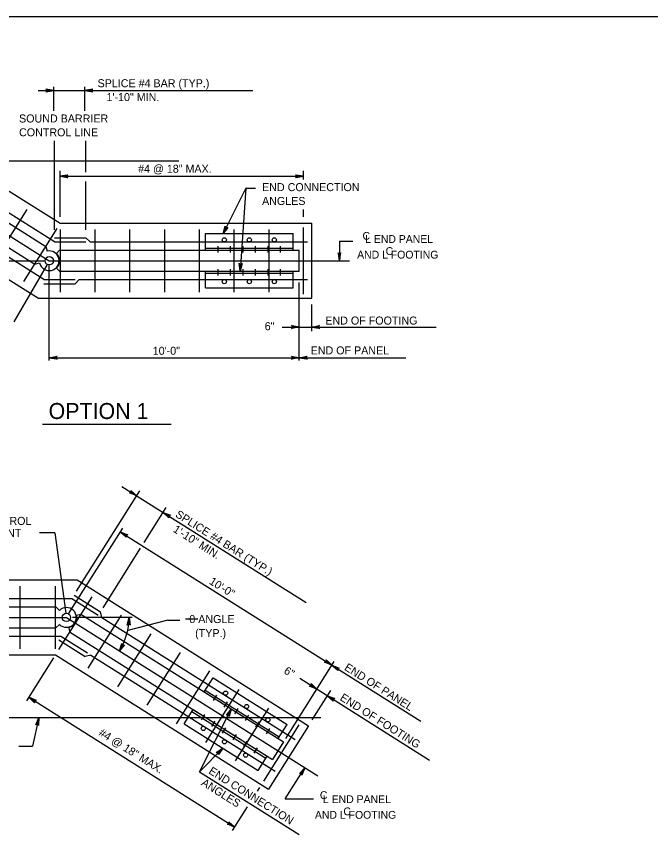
# Model space of a CAD drawing. Extents: x 3385 to 6532, y -616 to 1166.
# Drawn here: x 5641 to 5884.5, y -351.4 to -37.3 of the extents above; entities that cross this region are included whole.
import ezdxf

# ---------------------------------------------------------------- set-up
doc = ezdxf.new("R2010")
doc.units = 0
doc.layers.add('1', color=7, linetype='Continuous')
doc.layers.add('2', color=7, linetype='Continuous')

msp = doc.modelspace()

# ---------------------------------------------------------------- linework, layer by layer
at = {"layer": '1'}
for p, q in [((5649.41, -65.78), (5731.79, -65.78)), ((5655.36, -73.58), (5655.36, -64.39)), ((5667.36, -73.58), (5667.36, -64.39)), ((5565.2, -75.36), (5653.63, -131.12)), ((5655.72, -119.26), (5655.72, -85.08)), ((5667.72, -97.07), (5667.72, -85.08)), ((5616.77, -90.85), (5657.79, -116.72)), ((5554.94, -92.72), (5703.36, -92.72)), ((5655.71, -123.92), (5612.93, -96.94)), ((5657.79, -114.23), (5657.79, -96.66)), ((5751.24, -99.9), (5751.24, -96.66)), ((5611.22, -99.65), (5652.38, -125.6)), ((5657.79, -98.7), (5751.24, -98.7)), ((5667.72, -119.26), (5667.72, -100.7)), ((5729.06, -103.25), (5720.37, -120.72)), ((5729.06, -103.25), (5726.94, -135.12)), ((5729.06, -103.25), (5732.82, -103.25)), ((5606.95, -106.42), (5648.11, -132.37)), ((5651.55, -138.32), (5605.25, -109.12)), ((5645.01, -111.5), (5632.21, -131.8)), ((5751.24, -114.23), (5751.24, -111.41)), ((5601.41, -115.21), (5649.47, -145.52)), ((5656.51, -118.75), (5643.71, -139.05)), ((5657.79, -116.72), (5754.44, -116.72)), ((5657.79, -119.12), (5657.79, -143.12)), ((5671.14, -119.12), (5671.14, -143.12)), ((5684.49, -119.12), (5684.49, -143.12)), ((5697.84, -119.12), (5697.84, -143.12)), ((5711.19, -119.12), (5711.19, -143.12)), ((5724.54, -119.12), (5724.54, -143.12)), ((5737.89, -119.12), (5737.89, -143.12)), ((5751.24, -143.92), (5751.24, -118.32)), ((5754.44, -145.52), (5754.44, -116.72)), ((5655.71, -122.32), (5667.72, -122.32)), ((5669.32, -123.92), (5667.72, -122.32)), ((5713.63, -127.12), (5713.63, -120.72)), ((5713.63, -120.72), (5747.24, -120.72)), ((5747.24, -127.12), (5747.24, -120.72)), ((5652.38, -125.6), (5652.79, -127.41)), ((5655.71, -123.92), (5667.72, -123.92)), ((5669.32, -123.92), (5752.84, -123.92)), ((5718.44, -127.92), (5718.44, -125.52)), ((5723.24, -127.92), (5723.24, -125.52)), ((5728.04, -127.92), (5728.04, -125.52)), ((5732.84, -127.92), (5732.84, -125.52)), ((5737.64, -127.92), (5737.64, -125.52)), ((5742.44, -127.92), (5742.44, -125.52)), ((5765.08, -123.57), (5770.17, -123.57)), ((5765.08, -123.57), (5765.08, -131.12)), ((5656.46, -128.29), (5657.63, -127.12)), ((5657.63, -127.12), (5749.64, -127.12)), ((5713.63, -126.32), (5747.24, -126.32)), ((5713.63, -127.12), (5747.24, -127.12)), ((5749.64, -135.12), (5749.64, -127.12)), ((5628.32, -131.12), (5652.03, -131.12)), ((5653.63, -131.12), (5653.63, -131.12)), ((5653.63, -131.12), (5768.94, -131.12)), ((5652.83, -132.5), (5640.07, -154.59)), ((5648.12, -132.37), (5649.93, -131.96)), ((5653.63, -169.46), (5653.63, -132.72)), ((5656.46, -133.95), (5657.63, -135.12)), ((5718.44, -136.72), (5718.44, -134.32)), ((5723.24, -136.72), (5723.24, -134.32)), ((5728.04, -136.72), (5728.04, -134.32)), ((5732.84, -136.72), (5732.84, -134.32)), ((5737.64, -136.72), (5737.64, -134.32)), ((5742.44, -136.72), (5742.44, -134.32)), ((5657.63, -135.12), (5749.64, -135.12)), ((5713.63, -141.52), (5713.63, -135.12)), ((5713.63, -135.12), (5747.24, -135.12)), ((5713.63, -135.92), (5747.24, -135.92)), ((5747.24, -141.52), (5747.24, -135.12)), ((5651.55, -138.32), (5663.56, -138.32)), ((5651.55, -139.92), (5663.56, -139.92)), ((5665.16, -138.32), (5663.56, -139.92)), ((5665.16, -138.32), (5752.84, -138.32)), ((5749.64, -169.46), (5749.64, -139.49)), ((5713.63, -141.52), (5747.24, -141.52)), ((5649.47, -145.52), (5754.44, -145.52)), ((5754.44, -158.18), (5754.44, -147.93)), ((5743, -156.56), (5802.15, -156.56)), ((5653.63, -168.37), (5790.52, -168.37)), ((5651.07, -193.79), (5700.5, -193.79)), ((5664.15, -257.91), (5688.38, -219.49)), ((5681.55, -217.73), (5752.25, -262.31)), ((5690.07, -239.31), (5698.53, -225.89)), ((5655.76, -235.56), (5649.85, -235.56)), ((5655.76, -235.56), (5660.01, -266.44)), ((5661.09, -266.67), (5681.85, -233.74)), ((5680.93, -235.19), (5796.26, -307.9)), ((5674.31, -264.31), (5688.69, -241.49)), ((5602.42, -253.63), (5664.39, -253.63)), ((5664.39, -253.63), (5753.18, -309.61)), ((5642.5, -280.03), (5642.5, -256.03)), ((5656.07, -280.03), (5656.07, -256.03)), ((5657.35, -280.4), (5670.15, -260.09)), ((5663.17, -259.47), (5673.32, -265.87)), ((5602.42, -260.83), (5662.31, -260.83)), ((5662.31, -260.83), (5672.47, -267.23)), ((5602.42, -264.03), (5656.23, -264.03)), ((5656.23, -264.03), (5657.55, -265.34)), ((5664.13, -267.14), (5665.75, -266.78)), ((5665.75, -266.78), (5743.58, -315.84)), ((5673.82, -268.08), (5673.32, -265.87)), ((5564.37, -268.03), (5660.23, -268.03)), ((5660.23, -268.03), (5756.75, -328.88)), ((5660.23, -268.03), (5660.23, -268.03)), ((5685.5, -268.03), (5662.63, -268.03)), ((5668.64, -287.52), (5681.44, -267.21)), ((5673.82, -268.08), (5747.99, -314.84)), ((5699.22, -269.15), (5683.75, -273.09)), ((5699.22, -269.15), (5703.77, -269.15)), ((5710.7, -268.7), (5705.92, -268.7)), ((5602.42, -272.03), (5656.23, -272.03)), ((5656.23, -272.03), (5657.55, -270.71)), ((5661.12, -271.93), (5661.48, -273.54)), ((5602.42, -275.23), (5658.15, -275.23)), ((5658.15, -275.23), (5668.31, -281.63)), ((5661.48, -273.55), (5739.31, -322.61)), ((5679.94, -294.64), (5692.74, -274.33)), ((5657.3, -276.58), (5667.45, -282.98)), ((5602.42, -282.43), (5656.07, -282.43)), ((5656.07, -282.43), (5737.82, -333.97)), ((5669.66, -282.48), (5667.45, -282.98)), ((5669.66, -282.48), (5740.31, -327.02)), ((5691.23, -301.75), (5704.03, -281.45)), ((5645, -299.99), (5655.39, -283.51)), ((5744.44, -314.47), (5763.06, -284.94)), ((5702.52, -308.87), (5715.32, -288.57)), ((5713.12, -296.64), (5716.54, -291.23)), ((5716.54, -291.23), (5744.96, -309.15)), ((5749.79, -291.36), (5799.64, -322.79)), ((5713.12, -296.64), (5741.55, -314.56)), ((5713.55, -295.96), (5741.97, -313.88)), ((5713.81, -315.99), (5726.61, -295.69)), ((5716.75, -299.88), (5718.03, -297.85)), ((5754.64, -307.3), (5761.7, -296.09)), ((5645.82, -298.69), (5724.86, -348.53)), ((5720.81, -302.44), (5722.09, -300.41)), ((5705.44, -308.83), (5708.85, -303.41)), ((5708.43, -304.09), (5736.85, -322.01)), ((5708.85, -303.41), (5737.28, -321.33)), ((5711.36, -327.3), (5723.52, -303.19)), ((5724.87, -305), (5726.15, -302.97)), ((5725.1, -323.11), (5737.9, -302.81)), ((5602.42, -306.43), (5757.95, -306.43)), ((5649.69, -306.43), (5647.16, -317.45)), ((5712.06, -307.33), (5713.34, -305.3)), ((5728.93, -307.56), (5730.21, -305.53)), ((5705.44, -308.83), (5733.86, -326.75)), ((5716.12, -309.89), (5717.4, -307.86)), ((5720.18, -312.45), (5721.46, -310.42)), ((5733, -310.12), (5734.27, -308.09)), ((5735.97, -330.91), (5749.62, -309.25)), ((5737.06, -312.68), (5738.34, -310.65)), ((5753.18, -309.61), (5737.82, -333.97)), ((5741.55, -314.56), (5744.96, -309.15)), ((5724.24, -315.01), (5725.52, -312.98)), ((5728.3, -317.57), (5729.58, -315.54)), ((5743.58, -315.84), (5739.31, -322.61)), ((5641.97, -317.45), (5647.16, -317.45)), ((5711.36, -327.3), (5720.26, -318.17)), ((5732.36, -320.13), (5733.64, -318.1)), ((5733.86, -326.75), (5737.28, -321.33)), ((5744.21, -337.69), (5751.75, -325.73)), ((5711.36, -327.3), (5749.61, -351.41)), ((5733.59, -334.67), (5734.45, -333.31)), ((5744.21, -337.69), (5755.07, -337.69)), ((5724.04, -349.83), (5729.8, -340.69))]:
    msp.add_line(p, q, dxfattribs=at)
for points in [[(5655.36, -65.78), (5652.38, -65.22), (5652.61, -65.38), (5652.73, -65.58), (5652.76, -65.78), (5652.73, -65.98), (5652.61, -66.18), (5652.38, -66.34), (5655.36, -65.78), (5652.61, -66.18), (5652.73, -65.98), (5655.36, -65.78), (5652.76, -65.78), (5652.73, -65.58), (5655.36, -65.78), (5652.61, -65.38)], [(5667.36, -65.78), (5670.34, -66.34), (5670.11, -66.18), (5670, -65.98), (5669.96, -65.78), (5670, -65.58), (5670.11, -65.38), (5670.34, -65.22), (5667.36, -65.78), (5670.11, -65.38), (5670, -65.58), (5667.36, -65.78), (5669.96, -65.78), (5670, -65.98), (5667.36, -65.78), (5670.11, -66.18)], [(5657.79, -98.7), (5660.78, -98.14), (5660.66, -98.22), (5660.55, -98.3), (5660.49, -98.4), (5660.43, -98.5), (5660.41, -98.6), (5660.39, -98.7), (5660.41, -98.8), (5660.43, -98.9), (5660.49, -99), (5660.55, -99.1), (5660.66, -99.18), (5660.78, -99.26), (5657.79, -98.7), (5660.66, -99.18), (5660.55, -99.1), (5657.79, -98.7), (5660.49, -99), (5660.43, -98.9), (5657.79, -98.7), (5660.41, -98.8), (5660.39, -98.7), (5657.79, -98.7), (5660.41, -98.6), (5660.43, -98.5), (5657.79, -98.7), (5660.49, -98.4), (5660.55, -98.3), (5657.79, -98.7), (5660.66, -98.22)], [(5751.24, -98.7), (5748.26, -99.26), (5748.37, -99.18), (5748.49, -99.1), (5748.55, -99), (5748.6, -98.9), (5748.62, -98.8), (5748.64, -98.7), (5748.62, -98.6), (5748.6, -98.5), (5748.55, -98.4), (5748.49, -98.3), (5748.37, -98.22), (5748.26, -98.14), (5751.24, -98.7), (5748.37, -98.22), (5748.49, -98.3), (5751.24, -98.7), (5748.55, -98.4), (5748.6, -98.5), (5751.24, -98.7), (5748.62, -98.6), (5748.64, -98.7), (5751.24, -98.7), (5748.62, -98.8), (5748.6, -98.9), (5751.24, -98.7), (5748.55, -99), (5748.49, -99.1), (5751.24, -98.7), (5748.37, -99.18)], [(5720.37, -120.72), (5721.2, -117.8), (5721.22, -117.94), (5721.24, -118.07), (5721.3, -118.17), (5721.37, -118.27), (5721.45, -118.33), (5721.53, -118.39), (5721.63, -118.42), (5721.73, -118.45), (5721.84, -118.44), (5721.96, -118.43), (5722.08, -118.36), (5722.2, -118.3), (5720.37, -120.72), (5722.08, -118.36), (5721.96, -118.43), (5720.37, -120.72), (5721.84, -118.44), (5721.73, -118.45), (5720.37, -120.72), (5721.63, -118.42), (5721.53, -118.39), (5720.37, -120.72), (5721.45, -118.33), (5721.37, -118.27), (5720.37, -120.72), (5721.3, -118.17), (5721.24, -118.07), (5720.37, -120.72), (5721.22, -117.94)], [(5765.08, -131.12), (5765.64, -128.14), (5765.48, -128.37), (5765.28, -128.48), (5765.08, -128.52), (5764.88, -128.48), (5764.68, -128.37), (5764.53, -128.14), (5765.08, -131.12), (5764.68, -128.37), (5764.88, -128.48), (5765.08, -131.12), (5765.08, -128.52), (5765.28, -128.48), (5765.08, -131.12), (5765.48, -128.37)], [(5726.94, -135.12), (5726.58, -132.11), (5726.72, -132.35), (5726.91, -132.48), (5727.11, -132.52), (5727.31, -132.5), (5727.52, -132.4), (5727.69, -132.18), (5726.94, -135.12), (5727.52, -132.4), (5727.31, -132.5), (5726.94, -135.12), (5727.11, -132.52), (5726.91, -132.48), (5726.94, -135.12), (5726.72, -132.35)], [(5749.64, -156.56), (5746.65, -157.12), (5746.88, -156.96), (5747, -156.76), (5747.04, -156.56), (5747, -156.36), (5746.88, -156.16), (5746.65, -156), (5749.64, -156.56), (5746.88, -156.16), (5747, -156.36), (5749.64, -156.56), (5747.04, -156.56), (5747, -156.76), (5749.64, -156.56), (5746.88, -156.96)], [(5754.44, -156.56), (5757.42, -156), (5757.19, -156.16), (5757.07, -156.36), (5757.04, -156.56), (5757.07, -156.76), (5757.19, -156.96), (5757.42, -157.12), (5754.44, -156.56), (5757.19, -156.96), (5757.07, -156.76), (5754.44, -156.56), (5757.04, -156.56), (5757.07, -156.36), (5754.44, -156.56), (5757.19, -156.16)], [(5653.63, -168.37), (5656.62, -167.81), (5656.39, -167.97), (5656.27, -168.17), (5656.23, -168.37), (5656.27, -168.57), (5656.39, -168.77), (5656.62, -168.93), (5653.63, -168.37), (5656.39, -168.77), (5656.27, -168.57), (5653.63, -168.37), (5656.23, -168.37), (5656.27, -168.17), (5653.63, -168.37), (5656.39, -167.97)], [(5749.64, -168.37), (5746.65, -168.93), (5746.88, -168.77), (5747, -168.57), (5747.04, -168.37), (5747, -168.17), (5746.88, -167.97), (5746.65, -167.81), (5749.64, -168.37), (5746.88, -167.97), (5747, -168.17), (5749.64, -168.37), (5747.04, -168.37), (5747, -168.57), (5749.64, -168.37), (5746.88, -168.77)], [(5749.64, -168.37), (5752.62, -167.81), (5752.39, -167.97), (5752.27, -168.17), (5752.24, -168.37), (5752.27, -168.57), (5752.39, -168.77), (5752.62, -168.93), (5749.64, -168.37), (5752.39, -168.77), (5752.27, -168.57), (5749.64, -168.37), (5752.24, -168.37), (5752.27, -168.17), (5749.64, -168.37), (5752.39, -167.97)], [(5687.23, -221.31), (5684.41, -220.19), (5684.69, -220.18), (5684.89, -220.07), (5685.03, -219.92), (5685.11, -219.74), (5685.11, -219.5), (5685, -219.25), (5687.23, -221.31), (5685.11, -219.5), (5685.11, -219.74), (5687.23, -221.31), (5685.03, -219.92), (5684.89, -220.07), (5687.23, -221.31), (5684.69, -220.18)], [(5697.38, -227.71), (5700.2, -228.83), (5699.92, -228.84), (5699.72, -228.95), (5699.58, -229.1), (5699.5, -229.29), (5699.5, -229.52), (5699.61, -229.78), (5697.38, -227.71), (5699.5, -229.52), (5699.5, -229.29), (5697.38, -227.71), (5699.58, -229.1), (5699.72, -228.95), (5697.38, -227.71), (5699.92, -228.84)], [(5680.93, -235.19), (5683.76, -236.31), (5683.48, -236.32), (5683.27, -236.43), (5683.13, -236.58), (5683.06, -236.77), (5683.05, -237), (5683.16, -237.26), (5680.93, -235.19), (5683.05, -237), (5683.06, -236.77), (5680.93, -235.19), (5683.13, -236.58), (5683.27, -236.43), (5680.93, -235.19), (5683.48, -236.32)], [(5684.29, -268.03), (5684.68, -271.04), (5684.53, -270.8), (5684.34, -270.67), (5684.14, -270.62), (5683.94, -270.65), (5683.74, -270.75), (5683.56, -270.97), (5684.29, -268.03), (5683.74, -270.75), (5683.94, -270.65), (5684.29, -268.03), (5684.14, -270.62), (5684.34, -270.67), (5684.29, -268.03), (5684.53, -270.8)], [(5680.59, -280.86), (5681.54, -277.98), (5681.57, -278.26), (5681.69, -278.46), (5681.84, -278.58), (5682.04, -278.65), (5682.27, -278.64), (5682.52, -278.52), (5680.59, -280.86), (5682.27, -278.64), (5682.04, -278.65), (5680.59, -280.86), (5681.84, -278.58), (5681.69, -278.46), (5680.59, -280.86), (5681.57, -278.26)], [(5762.14, -286.39), (5759.32, -285.27), (5759.6, -285.26), (5759.81, -285.16), (5759.94, -285.01), (5760.02, -284.82), (5760.03, -284.59), (5759.92, -284.33), (5762.14, -286.39), (5760.03, -284.59), (5760.02, -284.82), (5762.14, -286.39), (5759.94, -285.01), (5759.81, -285.16), (5762.14, -286.39), (5759.6, -285.26)], [(5762.14, -286.39), (5764.96, -287.51), (5764.68, -287.52), (5764.48, -287.63), (5764.34, -287.78), (5764.26, -287.97), (5764.26, -288.2), (5764.37, -288.46), (5762.14, -286.39), (5764.26, -288.2), (5764.26, -287.97), (5762.14, -286.39), (5764.34, -287.78), (5764.48, -287.63), (5762.14, -286.39), (5764.68, -287.52)], [(5756.39, -295.52), (5753.57, -294.4), (5753.85, -294.39), (5754.05, -294.29), (5754.19, -294.13), (5754.27, -293.95), (5754.27, -293.71), (5754.16, -293.46), (5756.39, -295.52), (5754.27, -293.71), (5754.27, -293.95), (5756.39, -295.52), (5754.19, -294.13), (5754.05, -294.29), (5756.39, -295.52), (5753.85, -294.39)], [(5760.45, -298.08), (5763.27, -299.2), (5762.99, -299.21), (5762.78, -299.32), (5762.65, -299.47), (5762.57, -299.66), (5762.56, -299.89), (5762.67, -300.14), (5760.45, -298.08), (5762.56, -299.89), (5762.57, -299.66), (5760.45, -298.08), (5762.65, -299.47), (5762.78, -299.32), (5760.45, -298.08), (5762.99, -299.21)], [(5645.82, -298.69), (5648.64, -299.81), (5648.5, -299.82), (5648.36, -299.82), (5648.26, -299.87), (5648.15, -299.93), (5648.08, -300), (5648.02, -300.08), (5647.98, -300.17), (5647.94, -300.27), (5647.94, -300.38), (5647.93, -300.5), (5647.99, -300.63), (5648.04, -300.76), (5645.82, -298.69), (5647.99, -300.63), (5647.93, -300.5), (5645.82, -298.69), (5647.94, -300.38), (5647.94, -300.27), (5645.82, -298.69), (5647.98, -300.17), (5648.02, -300.08), (5645.82, -298.69), (5648.08, -300), (5648.15, -299.93), (5645.82, -298.69), (5648.26, -299.87), (5648.36, -299.82), (5645.82, -298.69), (5648.5, -299.82)], [(5723.52, -303.19), (5722.67, -306.11), (5722.65, -305.97), (5722.63, -305.83), (5722.57, -305.73), (5722.51, -305.64), (5722.43, -305.57), (5722.34, -305.51), (5722.25, -305.48), (5722.15, -305.46), (5722.03, -305.46), (5721.92, -305.47), (5721.8, -305.54), (5721.67, -305.6), (5723.52, -303.19), (5721.8, -305.54), (5721.92, -305.47), (5723.52, -303.19), (5722.03, -305.46), (5722.15, -305.46), (5723.52, -303.19), (5722.25, -305.48), (5722.34, -305.51), (5723.52, -303.19), (5722.43, -305.57), (5722.51, -305.64), (5723.52, -303.19), (5722.57, -305.73), (5722.63, -305.83), (5723.52, -303.19), (5722.65, -305.97)], [(5649.69, -306.43), (5649.57, -309.46), (5649.47, -309.2), (5649.3, -309.04), (5649.11, -308.96), (5648.91, -308.95), (5648.69, -309.02), (5648.48, -309.21), (5649.69, -306.43), (5648.69, -309.02), (5648.91, -308.95), (5649.69, -306.43), (5649.11, -308.96), (5649.3, -309.04), (5649.69, -306.43), (5649.47, -309.2)], [(5720.26, -318.17), (5718.58, -320.7), (5718.63, -320.42), (5718.57, -320.2), (5718.45, -320.03), (5718.28, -319.92), (5718.05, -319.86), (5717.78, -319.92), (5720.26, -318.17), (5718.05, -319.86), (5718.28, -319.92), (5720.26, -318.17), (5718.45, -320.03), (5718.57, -320.2), (5720.26, -318.17), (5718.63, -320.42)], [(5751.75, -325.73), (5750.64, -328.55), (5750.62, -328.27), (5750.52, -328.06), (5750.37, -327.93), (5750.18, -327.85), (5749.95, -327.84), (5749.69, -327.95), (5751.75, -325.73), (5749.95, -327.84), (5750.18, -327.85), (5751.75, -325.73), (5750.37, -327.93), (5750.52, -328.06), (5751.75, -325.73), (5750.62, -328.27)], [(5724.86, -348.53), (5722.04, -347.41), (5722.18, -347.4), (5722.32, -347.4), (5722.42, -347.34), (5722.52, -347.29), (5722.59, -347.22), (5722.66, -347.14), (5722.7, -347.05), (5722.74, -346.95), (5722.74, -346.84), (5722.74, -346.72), (5722.69, -346.59), (5722.63, -346.46), (5724.86, -348.53), (5722.69, -346.59), (5722.74, -346.72), (5724.86, -348.53), (5722.74, -346.84), (5722.74, -346.95), (5724.86, -348.53), (5722.7, -347.05), (5722.66, -347.14), (5724.86, -348.53), (5722.59, -347.22), (5722.52, -347.29), (5724.86, -348.53), (5722.42, -347.34), (5722.32, -347.4), (5724.86, -348.53), (5722.18, -347.4)]]:
    msp.add_lwpolyline(points, dxfattribs=at)
for centre, radius in [((5720.84, -123.12), 0.801), ((5730.44, -123.12), 0.801), ((5740.04, -123.12), 0.801), ((5653.63, -131.12), 1.6), ((5720.84, -139.12), 0.801), ((5730.44, -139.12), 0.801), ((5740.04, -139.12), 0.801), ((5660.23, -268.03), 1.6), ((5721.34, -297.1), 0.801), ((5729.46, -302.22), 0.801), ((5737.59, -307.34), 0.801), ((5712.81, -310.64), 0.801), ((5720.93, -315.76), 0.801), ((5729.05, -320.88), 0.801)]:
    msp.add_circle(centre, radius, dxfattribs=at)
for centre, radius, start, end in [((5653.63, -131.12), 3.8, 192.769, 102.769), ((5653.63, -131.12), 4, 314.9982, 45.0007), ((5660.23, -268.03), 3.8, 225, 135), ((5660.23, -268.03), 4, 282.7683, 12.7708), ((5660.23, -268.03), 24.06, 327.769, 0)]:
    msp.add_arc(centre, radius, start, end, dxfattribs=at)
at = {"layer": '2'}
msp.add_line((5483.34, -37.31), (6269.34, -37.31), dxfattribs=at)

# ---------------------------------------------------------------- texts
at = {"layer": '1'}
for s, height, p in [('SPLICE #4 BAR (TYP.)', 3.0721, (5672.2, -64.51)), ('   1\'-10" MIN.', 3.0721, (5672.2, -69.83)), ('SOUND BARRIER', 3.0721, (5642.05, -78.04)), ('CONTROL LINE', 3.0721, (5642.05, -83.35)), ('#4 @ 18" MAX.', 3.0721, (5687.77, -97.34)), ('END CONNECTION', 3.0721, (5735.34, -104.4)), ('ANGLES', 3.072, (5735.34, -109.71)), ('C', 3, (5773.92, -123.06)), ('L END PANEL', 3, (5774.92, -124.28)), ('AND L FOOTING', 3, (5771.84, -130.28)), ('C', 3, (5782.78, -128.91)), ('END OF FOOTING', 3.0721, (5759.63, -155.61)), ('6"', 3.072, (5736.35, -157.79)), ('10\'-0"', 3.072, (5693.37, -167.21)), ('END OF PANEL', 3.0721, (5753.99, -167.07)), ('OPTION 1', 6.144, (5653.38, -191.87)), ('LAYOUT CONTROL', 3.0721, (5609.14, -232.52)), ('WORKING POINT', 3.0721, (5609.14, -237.13)), ('0 ANGLE', 3.072, (5707.42, -270.2)), ('(TYP.)', 3.072, (5709.66, -275.58)), ('C', 3, (5757.54, -337.75)), ('L END PANEL', 3, (5758.72, -339.32)), ('AND L FOOTING', 3, (5755.64, -345.32)), ('C', 3, (5766.56, -343.98))]:
    msp.add_text(s, height=height, dxfattribs=at).set_placement(p)
for s, height, p in [('SPLICE #4 BAR (TYP.)', 3.0721, (5701.8, -229.25)), ('  1\'-10" MIN.', 3.0721, (5698.97, -233.75)), ('10\'-0"', 3.072, (5714.78, -254.94)), ('END OF PANEL', 3.0721, (5766.66, -288)), ('6"', 3.072, (5743.42, -289.27)), ('END OF FOOTING', 3.0721, (5764.96, -299.59)), ('#4 @ 18" MAX.', 3.0721, (5672.37, -313.06)), ('END CONNECTION', 3.0721, (5714.56, -327.75)), ('ANGLES', 3.072, (5711.73, -332.24))]:
    msp.add_text(s, height=height, rotation=327.769, dxfattribs=at).set_placement(p)

doc.saveas('drawing.dxf')
